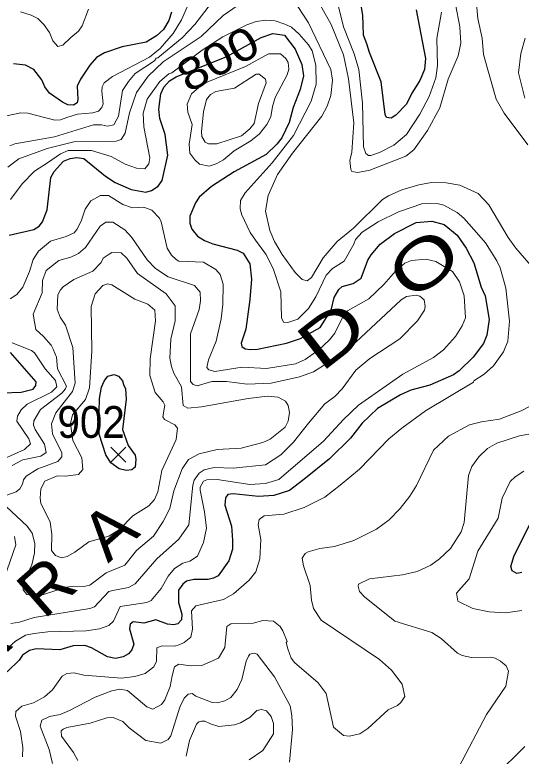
# Model space of a CAD drawing. Extents: x 294.2 to 320.3, y 7482.7 to 7510.7.
# Drawn here: x 307.293 to 308.568, y 7485.877 to 7487.743 of the extents above; entities that cross this region are included whole.
import ezdxf
from ezdxf.enums import TextEntityAlignment as Align

# ---------------------------------------------------------------- set-up
doc = ezdxf.new("R2010")
doc.units = 0
doc.header["$LTSCALE"] = 0.032
for name, color, linetype, lineweight in [('1', 7, 'Continuous', 25), ('2', 7, 'Continuous', 13), ('21', 7, 'Continuous', 25)]:
    doc.layers.add(name, color=color, linetype=linetype, lineweight=lineweight)
doc.layers.add('61', color=7, linetype='Continuous')

msp = doc.modelspace()

# ---------------------------------------------------------------- linework, layer by layer
at = {"layer": '1'}
for points in [[(308.1796, 7487.6694), (308.1712, 7487.6914), (308.1697, 7487.7183), (308.1691, 7487.7409), (308.1586, 7487.8093)], [(308.3036, 7487.7552), (308.3268, 7487.6325), (308.324, 7487.605), (308.3123, 7487.5776), (308.2922, 7487.5453), (308.2795, 7487.5179), (308.2523, 7487.4904)], [(307.6875, 7487.7491), (307.6808, 7487.7286), (307.6675, 7487.706), (307.6497, 7487.6899), (307.6236, 7487.6742), (307.5631, 7487.6624), (307.5193, 7487.6473), (307.4988, 7487.635), (307.4816, 7487.6162), (307.4589, 7487.5807), (307.4505, 7487.5629), (307.4522, 7487.5295), (307.45, 7487.5214), (307.4412, 7487.5155), (307.4267, 7487.5165), (307.4134, 7487.5225), (307.3806, 7487.5457), (307.3689, 7487.5618), (307.3612, 7487.579), (307.3412, 7487.6048), (307.3201, 7487.6156), (307.2895, 7487.6194)], [(307.2792, 7487.188), (307.3413, 7487.202), (307.3543, 7487.2111), (307.3632, 7487.2219), (307.3743, 7487.2515), (307.3842, 7487.3329), (307.3925, 7487.348), (307.416, 7487.3743), (307.4327, 7487.3813), (307.4493, 7487.384), (307.467, 7487.3808), (307.5211, 7487.3367), (307.546, 7487.3205), (307.586, 7487.3028), (307.6226, 7487.2964), (307.6376, 7487.3002), (307.6537, 7487.3115), (307.6643, 7487.3254), (307.6784, 7487.3895), (307.6718, 7487.4416), (307.6585, 7487.482), (307.6557, 7487.5056), (307.6606, 7487.5437), (307.6684, 7487.5604), (307.6822, 7487.5766), (307.6994, 7487.5868), (307.8267, 7487.6374), (307.9129, 7487.6858), (307.9427, 7487.696), (307.9716, 7487.6917), (307.9988, 7487.6562), (308.016, 7487.6175)], [(308.2523, 7487.4904), (308.2407, 7487.4824), (308.229, 7487.4845), (308.2251, 7487.492), (308.2157, 7487.5738), (308.1863, 7487.6479), (308.1796, 7487.6694)], [(308.016, 7487.6175), (308.0202, 7487.589), (308.0118, 7487.5551), (307.9938, 7487.5094), (307.9838, 7487.4713), (307.9649, 7487.4331), (307.9524, 7487.417)], [(307.9524, 7487.417), (307.9258, 7487.3912), (307.8451, 7487.3471), (307.7886, 7487.3104), (307.7575, 7487.2835), (307.7481, 7487.2696), (307.7334, 7487.2357), (307.7334, 7487.2185), (307.7389, 7487.2029), (307.7534, 7487.1857), (307.7703, 7487.1744), (307.7919, 7487.1663), (307.8532, 7487.1507), (307.8676, 7487.1432), (307.8849, 7487.1159), (307.8887, 7487.0776), (307.8845, 7487.0265), (307.8743, 7486.9517), (307.8632, 7486.9162), (307.8648, 7486.9076), (307.8731, 7486.9022), (307.8859, 7486.9001), (307.9037, 7486.9011), (307.9769, 7486.9162), (308.0127, 7486.928), (308.0615, 7486.9555), (308.0895, 7486.9996), (308.0973, 7487.0313), (308.1087, 7487.0512), (308.117, 7487.0587), (308.1447, 7487.0662), (308.1652, 7487.0797), (308.1819, 7487.1248), (308.1899, 7487.1388), (308.2127, 7487.1657), (308.2493, 7487.192), (308.3034, 7487.22), (308.3428, 7487.2232), (308.3736, 7487.2146), (308.4069, 7487.1877), (308.4296, 7487.1554), (308.4482, 7487.1183), (308.467, 7487.057), (308.4767, 7487.0355), (308.4872, 7486.9758), (308.4809, 7486.9365), (308.4726, 7486.9156), (308.4465, 7486.8806), (308.4118, 7486.8462), (308.3974, 7486.8365), (308.3381, 7486.8107), (308.2896, 7486.7978), (308.2641, 7486.7865), (308.2061, 7486.7515), (308.1672, 7486.7149), (308.1382, 7486.6773), (308.0856, 7486.6247), (308.0207, 7486.5729), (307.9846, 7486.5455), (307.945, 7486.5325), (307.9062, 7486.5304), (307.8426, 7486.5374), (307.8293, 7486.5352), (307.8232, 7486.5272), (307.8216, 7486.5089), (307.8388, 7486.4556), (307.8407, 7486.4207), (307.8407, 7486.3976), (307.8318, 7486.3685), (307.8049, 7486.3304), (307.7933, 7486.3245), (307.78, 7486.3212), (307.7434, 7486.3218), (307.7256, 7486.3173), (307.7162, 7486.3098), (307.7056, 7486.2947), (307.7051, 7486.2635), (307.714, 7486.2339), (307.7126, 7486.2199), (307.7037, 7486.2097), (307.6938, 7486.207), (307.6777, 7486.2086), (307.6483, 7486.2199), (307.6181, 7486.2118), (307.5914, 7486.2145), (307.5837, 7486.2092), (307.5815, 7486.1973), (307.5926, 7486.1586), (307.5876, 7486.1441), (307.5792, 7486.1339), (307.5656, 7486.1264), (307.5468, 7486.1226), (307.5268, 7486.1269), (307.4858, 7486.1495), (307.4694, 7486.1549)], [(307.2612, 7486.7911), (307.3089, 7486.7928), (307.3396, 7486.8008), (307.3463, 7486.8099), (307.3468, 7486.8191), (307.2822, 7486.8928)], [(308.5691, 7486.3388), (308.5569, 7486.3366), (308.5447, 7486.3436), (308.5414, 7486.3538), (308.5502, 7486.3819), (308.5924, 7486.4652)], [(307.4694, 7486.1549), (307.44, 7486.1543), (307.4068, 7486.1447), (307.3472, 7486.1469), (307.3305, 7486.1425), (307.3128, 7486.1307), (307.3045, 7486.1183)], [(307.3045, 7486.1183), (307.2751, 7486.0898), (307.2346, 7486.0704), (307.2205, 7486.0591), (307.2083, 7486.0397), (307.2022, 7486.0209), (307.2044, 7485.9994), (307.2324, 7485.9623), (307.2557, 7485.9215), (307.2578, 7485.8806), (307.2428, 7485.8499)]]:
    msp.add_lwpolyline(points, dxfattribs=at)
msp.add_lwpolyline([(307.5671, 7486.8119), (307.5716, 7486.8017), (307.5732, 7486.7753), (307.5641, 7486.699), (307.5786, 7486.6587), (307.5963, 7486.6345), (307.598, 7486.6237), (307.5958, 7486.6044), (307.5874, 7486.5974), (307.5736, 7486.5957), (307.5559, 7486.6), (307.5352, 7486.6147), (307.5219, 7486.6352), (307.5055, 7486.6874), (307.5044, 7486.7095), (307.5066, 7486.7773), (307.5117, 7486.8054), (307.5179, 7486.8205), (307.5274, 7486.8328), (307.5435, 7486.8371), (307.554, 7486.8328), (307.5645, 7486.8215)], close=True, dxfattribs=at)
at = {"layer": '2'}
for points in [[(307.769, 7487.8589), (307.7128, 7487.7299), (307.6917, 7487.6955), (307.6587, 7487.6577), (307.6325, 7487.6362), (307.5388, 7487.5878), (307.5185, 7487.5717), (307.5131, 7487.5617), (307.512, 7487.5509), (307.5154, 7487.5186), (307.5123, 7487.5094), (307.5035, 7487.5002), (307.4893, 7487.496), (307.4512, 7487.4929), (307.4239, 7487.4845), (307.4078, 7487.478), (307.3936, 7487.4772), (307.3261, 7487.4952), (307.308, 7487.496), (307.2722, 7487.4885)], [(308.3672, 7487.7491), (308.3557, 7487.6827), (308.357, 7487.615), (308.3531, 7487.5844), (308.3359, 7487.5371), (308.313, 7487.493), (308.2791, 7487.4418), (308.2475, 7487.4147), (308.2113, 7487.3958), (308.1897, 7487.3883), (308.1833, 7487.3883), (308.1769, 7487.3934), (308.1705, 7487.4107), (308.168, 7487.5205), (308.159, 7487.6048), (308.1475, 7487.6444), (308.1207, 7487.7121), (308.0901, 7487.8346)], [(307.2805, 7487.4126), (307.2933, 7487.4177), (307.3929, 7487.4356), (307.4912, 7487.4662), (307.5117, 7487.4662), (307.5263, 7487.4624), (307.5423, 7487.4656), (307.5538, 7487.4873), (307.5645, 7487.5523), (307.5795, 7487.5749), (307.5962, 7487.5953), (307.6444, 7487.6271), (307.6489, 7487.6335), (307.6534, 7487.6341), (307.7147, 7487.6846), (307.7466, 7487.7184), (307.8194, 7487.8142)], [(308.4502, 7487.8283), (308.4585, 7487.7338), (308.4693, 7487.684), (308.4726, 7487.643), (308.5051, 7487.5307), (308.5249, 7487.495), (308.5843, 7487.4158)], [(308.039, 7487.8091), (308.0895, 7487.7184)], [(307.2754, 7487.359), (307.3035, 7487.38), (307.375, 7487.4062), (307.4421, 7487.4234), (307.548, 7487.4247), (307.5608, 7487.4285), (307.571, 7487.4452), (307.5819, 7487.4962), (307.5997, 7487.5473), (307.6285, 7487.5882), (307.6663, 7487.6245), (307.7626, 7487.6884), (307.8175, 7487.7414), (307.8551, 7487.7669)], [(307.3074, 7487.7503), (307.3342, 7487.7421), (307.3508, 7487.7331), (307.3661, 7487.7184), (307.3808, 7487.698), (307.389, 7487.6769), (307.4012, 7487.6629), (307.414, 7487.6661), (307.4344, 7487.6859), (307.4536, 7487.7012), (307.4625, 7487.7146), (307.4784, 7487.7567)], [(308.0057, 7487.764), (308.032, 7487.7222), (308.0888, 7487.6048), (308.0926, 7487.578), (308.0888, 7487.5396), (308.0793, 7487.5128), (308.0658, 7487.4873), (307.9924, 7487.3947), (307.9541, 7487.3405), (307.9311, 7487.2881), (307.9241, 7487.2485), (307.935, 7487.2), (307.9465, 7487.1719), (307.9662, 7487.1393), (307.9988, 7487.094), (308.0161, 7487.0761)], [(308.1386, 7487.3532), (308.1418, 7487.3487), (308.1565, 7487.3462), (308.1872, 7487.3513), (308.2778, 7487.3871), (308.2976, 7487.403), (308.3321, 7487.4515), (308.3627, 7487.509), (308.3838, 7487.5805), (308.4093, 7487.6393), (308.4157, 7487.6712), (308.4132, 7487.7121), (308.4023, 7487.7695)], [(307.9727, 7487.7196), (307.9484, 7487.728), (307.9254, 7487.7293), (307.9011, 7487.7261), (307.8769, 7487.7178), (307.8169, 7487.6871), (307.7645, 7487.6539), (307.688, 7487.5963), (307.6808, 7487.5939), (307.6585, 7487.5747), (307.6266, 7487.5307), (307.6163, 7487.495), (307.6176, 7487.4605), (307.6329, 7487.3826), (307.6304, 7487.3679), (307.6202, 7487.3551), (307.5991, 7487.3564), (307.571, 7487.3672), (307.5359, 7487.3858), (307.4861, 7487.4011), (307.4272, 7487.4015), (307.4078, 7487.3929), (307.3756, 7487.3698), (307.3425, 7487.3494), (307.3118, 7487.3174), (307.2824, 7487.2779)], [(307.3878, 7486.0437), (307.4127, 7486.0782), (307.4242, 7486.0852), (307.4427, 7486.0864), (307.467, 7486.0807), (307.5615, 7486.0731), (307.5953, 7486.0769), (307.6215, 7486.0852), (307.6432, 7486.1012), (307.6495, 7486.1159), (307.6508, 7486.1495), (307.6642, 7486.1543), (307.6947, 7486.1538), (307.7069, 7486.157), (307.7198, 7486.1631), (307.7364, 7486.1765), (307.7402, 7486.1963), (307.7383, 7486.2429), (307.7492, 7486.255), (307.8186, 7486.2712), (307.8437, 7486.285), (307.8832, 7486.3195), (307.8998, 7486.3406), (307.91, 7486.3738), (307.9126, 7486.4217), (307.9056, 7486.4594), (307.9082, 7486.4721), (307.9209, 7486.4817), (307.9701, 7486.4861), (308.0212, 7486.5027), (308.0735, 7486.5283), (308.1125, 7486.5589), (308.161, 7486.5992), (308.235, 7486.6758), (308.267, 7486.7026), (308.327, 7486.746), (308.4476, 7486.8182), (308.4483, 7486.8214), (308.4745, 7486.8386), (308.4981, 7486.859), (308.523, 7486.8948), (308.5345, 7486.9216), (308.5383, 7486.9714), (308.5288, 7487.0544), (308.5147, 7487.1055), (308.5064, 7487.1234), (308.4777, 7487.1687), (308.4611, 7487.1885), (308.4234, 7487.2313), (308.4068, 7487.2453), (308.373, 7487.2638), (308.3596, 7487.267), (308.32, 7487.2676), (308.2587, 7487.2472), (308.2076, 7487.2217), (308.1673, 7487.1955), (308.1508, 7487.1776), (308.1469, 7487.1655), (308.122, 7487.1227), (308.0927, 7487.1042), (308.0767, 7487.087), (308.0505, 7487.0327), (308.0326, 7487.0033), (308.0052, 7486.9765), (307.9803, 7486.9682), (307.9694, 7486.9695), (307.9643, 7486.9804), (307.9624, 7487.0455), (307.9432, 7487.1042), (307.9248, 7487.14), (307.8986, 7487.1757), (307.8858, 7487.1949), (307.8641, 7487.2409), (307.8602, 7487.2549), (307.8615, 7487.2753), (307.873, 7487.2945), (307.9407, 7487.3698), (307.9943, 7487.4388), (308.039, 7487.5256), (308.0518, 7487.5678), (308.0505, 7487.6163), (308.0416, 7487.652), (308.0326, 7487.6674), (308.009, 7487.6942), (307.9893, 7487.7114), (307.9727, 7487.7196)], [(308.0895, 7487.7184), (308.1201, 7487.6418), (308.1329, 7487.5818), (308.1463, 7487.4707), (308.1412, 7487.3966), (308.1361, 7487.3762), (308.1386, 7487.3532)], [(308.5779, 7487.684), (308.5671, 7487.6456), (308.5613, 7487.5971), (308.5773, 7487.5326)], [(308.2191, 7487.2778), (308.2337, 7487.2875), (308.2676, 7487.3021), (308.3098, 7487.3149), (308.3417, 7487.3206), (308.3787, 7487.32), (308.4132, 7487.3136), (308.4592, 7487.2926), (308.486, 7487.2645), (308.5351, 7487.1821), (308.5543, 7487.1553), (308.6143, 7487.0857)], [(307.2818, 7487.0282), (307.2984, 7487.0391), (307.3131, 7487.0569), (307.3303, 7487.0966), (307.3392, 7487.1272), (307.3527, 7487.1476), (307.3827, 7487.1731), (307.4223, 7487.1846), (307.4427, 7487.1942), (307.4497, 7487.2025), (307.4605, 7487.223), (307.4702, 7487.2536), (307.4848, 7487.2741), (307.5091, 7487.2881), (307.5289, 7487.2881), (307.5653, 7487.2651), (307.5896, 7487.2568), (307.6177, 7487.2587), (307.638, 7487.2511), (307.6572, 7487.2306), (307.6617, 7487.2217), (307.677, 7487.1553), (307.6872, 7487.138), (307.6993, 7487.1266), (307.7064, 7487.1227), (307.7677, 7487.1202), (307.799, 7487.1016)], [(308.0161, 7487.0761), (308.0288, 7487.0735), (308.0403, 7487.0819), (308.0697, 7487.131), (308.1048, 7487.1719), (308.1456, 7487.2057), (308.2191, 7487.2778)], [(307.2862, 7486.6081), (307.3137, 7486.6228), (307.3584, 7486.6317), (307.3724, 7486.6407), (307.368, 7486.6624), (307.3443, 7486.6988), (307.3405, 7486.7096), (307.3412, 7486.7211), (307.3578, 7486.7492), (307.4114, 7486.79), (307.421, 7486.8009), (307.4229, 7486.808), (307.4005, 7486.8514), (307.398, 7486.8808), (307.3897, 7486.9012), (307.3846, 7486.9114), (307.3655, 7486.9331), (307.3463, 7486.951), (307.3392, 7486.9893), (307.3622, 7487.0429), (307.3629, 7487.0736), (307.3724, 7487.0991), (307.4037, 7487.1246), (307.4338, 7487.1329), (307.4535, 7487.1419), (307.4708, 7487.1572), (307.5078, 7487.2108), (307.5225, 7487.2204), (307.5398, 7487.2211), (307.5697, 7487.2019), (307.5876, 7487.1821), (307.626, 7487.1259), (307.647, 7487.1042), (307.679, 7487.0831), (307.7454, 7487.0614), (307.7594, 7487.0448), (307.7606, 7487.0225), (307.7575, 7487.0008), (307.7351, 7486.9395), (307.7358, 7486.8195), (307.742, 7486.8125), (307.7525, 7486.8092), (307.7894, 7486.8201), (307.8258, 7486.8201), (307.8782, 7486.813), (307.9382, 7486.8156), (308.0097, 7486.8316), (308.0454, 7486.8444), (308.1137, 7486.8878), (308.1514, 7486.9184), (308.2657, 7487.025), (308.2791, 7487.0339), (308.3034, 7487.0372), (308.3123, 7487.0346), (308.3238, 7487.0257), (308.3263, 7487.0084), (308.3244, 7486.9995)], [(307.2716, 7486.5053), (307.3239, 7486.4555), (307.3367, 7486.4377), (307.3437, 7486.4121), (307.3431, 7486.3879), (307.3361, 7486.3585), (307.3195, 7486.324), (307.315, 7486.3074), (307.3144, 7486.2953), (307.3233, 7486.2838), (307.3546, 7486.2805), (307.4236, 7486.3022), (307.4414, 7486.3048), (307.467, 7486.3035), (307.4823, 7486.3068), (307.5232, 7486.338), (307.5697, 7486.3572), (307.5991, 7486.3942), (307.6419, 7486.4306), (307.6668, 7486.467), (307.6834, 7486.5002), (307.6936, 7486.5449), (307.7141, 7486.5998), (307.7307, 7486.6234), (307.7568, 7486.6381), (307.8028, 7486.6483), (307.8628, 7486.6521), (307.9177, 7486.6662), (307.9356, 7486.6745), (307.9739, 7486.7051), (307.9815, 7486.7198), (307.9848, 7486.7416), (307.9815, 7486.7594), (307.9745, 7486.7703), (307.956, 7486.7805), (307.9292, 7486.7831), (307.8807, 7486.7773), (307.7632, 7486.7562), (307.7288, 7486.7524), (307.7172, 7486.7594), (307.7128, 7486.8066), (307.6936, 7486.8405), (307.6872, 7486.8578), (307.6834, 7486.8782), (307.686, 7486.9261), (307.6968, 7486.9727), (307.6969, 7487.01), (307.6741, 7487.0402), (307.6023, 7487.0914), (307.5755, 7487.1298), (307.5608, 7487.1438), (307.5378, 7487.1444), (307.5308, 7487.1406), (307.5155, 7487.1304), (307.5103, 7487.1195), (307.4893, 7487.0972), (307.4414, 7487.0768), (307.4146, 7487.0582), (307.4082, 7487.0506), (307.4012, 7487.0378), (307.3999, 7487.0021), (307.4076, 7486.9816), (307.4204, 7486.9612), (307.4395, 7486.905), (307.4452, 7486.8156), (307.4382, 7486.7945), (307.3967, 7486.7409), (307.3859, 7486.7135), (307.3884, 7486.6879), (307.4114, 7486.64), (307.4114, 7486.6298), (307.4018, 7486.6183), (307.3508, 7486.5998), (307.322, 7486.5816), (307.3148, 7486.5724), (307.3126, 7486.5611), (307.3059, 7486.5493), (307.2965, 7486.5423), (307.2729, 7486.5334)], [(307.7805, 7486.8744), (307.7766, 7486.8552), (307.7817, 7486.8488), (307.7964, 7486.845), (307.8654, 7486.8558), (307.9267, 7486.8526), (307.9995, 7486.8641), (308.0237, 7486.875), (308.0582, 7486.8993), (308.0856, 7486.9248), (308.0984, 7486.9414), (308.1207, 7486.9855), (308.1303, 7486.9976), (308.1846, 7487.0276), (308.2223, 7487.064), (308.251, 7487.0972), (308.2753, 7487.1176), (308.2919, 7487.1246), (308.3276, 7487.1278), (308.3532, 7487.1221), (308.3953, 7487.0965), (308.4126, 7487.0703), (308.424, 7487.0353), (308.4272, 7486.9797), (308.4189, 7486.9599), (308.4023, 7486.9331), (308.3723, 7486.8992), (308.3468, 7486.8801), (308.2702, 7486.8386), (308.1584, 7486.7601), (308.1207, 7486.7243), (308.0703, 7486.6694), (307.9574, 7486.5735), (307.9246, 7486.5627), (307.8847, 7486.5605), (307.8028, 7486.573), (307.7766, 7486.5724), (307.7677, 7486.5685), (307.76, 7486.5539), (307.76, 7486.5462), (307.7708, 7486.4913), (307.776, 7486.4504), (307.7683, 7486.4147), (307.753, 7486.3802), (307.7339, 7486.3674)], [(307.799, 7487.1016), (307.8098, 7487.0895), (307.8175, 7487.0646), (307.8168, 7487.0136), (307.813, 7486.9778), (307.8002, 7486.9216), (307.7805, 7486.8744)], [(308.3244, 7486.9995), (308.3072, 7486.9727), (308.2625, 7486.9273), (308.1872, 7486.8776), (308.1514, 7486.8482), (308.1169, 7486.8016), (308.0984, 7486.7824)], [(307.2652, 7486.6253), (307.3176, 7486.649), (307.3329, 7486.663), (307.3284, 7486.6758), (307.2984, 7486.7199), (307.3003, 7486.7326), (307.3093, 7486.7486), (307.3239, 7486.7626), (307.3859, 7486.7926), (307.3993, 7486.806), (307.3954, 7486.822), (307.3693, 7486.8514), (307.3431, 7486.8916), (307.3354, 7486.8974), (307.2869, 7486.9171)], [(308.6111, 7486.769), (308.5677, 7486.746), (308.5128, 7486.7249), (308.4681, 7486.7185), (308.4375, 7486.7103), (308.3845, 7486.6822), (308.3468, 7486.647), (308.304, 7486.5577), (308.2874, 7486.5309), (308.2631, 7486.5002), (308.2357, 7486.4715), (308.2038, 7486.4478), (308.1463, 7486.4197), (308.0978, 7486.4044), (308.0608, 7486.3993), (308.0314, 7486.391), (308.0243, 7486.3872), (308.0167, 7486.3751), (308.0199, 7486.3559), (308.0365, 7486.3061), (308.0397, 7486.2691), (308.0454, 7486.2487), (308.0639, 7486.2192), (308.2114, 7486.1203), (308.2414, 7486.0935), (308.2683, 7486.0577), (308.2746, 7486.0271), (308.265, 7486.0117), (308.2567, 7486.0041), (308.2331, 7485.9932), (308.1814, 7485.946), (308.1616, 7485.9326), (308.1348, 7485.9268), (308.1208, 7485.9288), (308.0952, 7485.9498), (308.0767, 7486.0341), (308.0569, 7486.0609), (307.9969, 7486.1126), (307.9892, 7486.1235), (307.9803, 7486.1465), (307.9764, 7486.1631), (307.9784, 7486.1657), (307.9675, 7486.1925), (307.9611, 7486.2027), (307.9439, 7486.2161), (307.9171, 7486.2186), (307.8935, 7486.2116), (307.8373, 7486.2097), (307.827, 7486.2033), (307.8219, 7486.1503), (307.806, 7486.1235), (307.7639, 7486.105), (307.7351, 7486.1037), (307.7058, 7486.1082), (307.6955, 7486.1018), (307.6891, 7486.0788), (307.684, 7486.052), (307.6706, 7486.0188), (307.6623, 7486.0066), (307.6406, 7485.9952), (307.6253, 7486.0009), (307.5768, 7486.0418), (307.5576, 7486.0456), (307.5372, 7486.0412), (307.4957, 7486.0252), (307.4312, 7485.9913), (307.407, 7485.9817), (307.3801, 7485.9766), (307.3609, 7485.9671), (307.3571, 7485.9524), (307.3795, 7485.8937), (307.3878, 7485.8579)], [(308.0984, 7486.7824), (308.0735, 7486.7632), (308.0326, 7486.7147)], [(308.0326, 7486.7147), (307.995, 7486.6668), (307.9624, 7486.6349), (307.9241, 7486.61), (307.8424, 7486.6017), (307.7947, 7486.6033), (307.7696, 7486.5972), (307.7568, 7486.5889), (307.7447, 7486.5711), (307.7415, 7486.559), (307.7313, 7486.4593), (307.7064, 7486.4229), (307.6508, 7486.3732), (307.5965, 7486.3106), (307.5793, 7486.3016), (307.5398, 7486.294), (307.5295, 7486.2908), (307.4938, 7486.2524), (307.4823, 7486.2486), (307.3418, 7486.2256), (307.3048, 7486.2141), (307.2831, 7486.211)], [(308.6482, 7486.6981), (308.5639, 7486.6828), (308.5064, 7486.6643), (308.4834, 7486.6509), (308.4611, 7486.6305), (308.4438, 7486.6062), (308.4355, 7486.5832), (308.424, 7486.4645), (308.4164, 7486.4415), (308.3896, 7486.3993), (308.3621, 7486.3732), (308.3404, 7486.3578), (308.3059, 7486.3418), (308.2689, 7486.3329), (308.1859, 7486.3233), (308.1584, 7486.31), (308.1572, 7486.3048), (308.161, 7486.2908), (308.1731, 7486.278), (308.2497, 7486.2161), (308.343, 7486.188), (308.366, 7486.1727), (308.4074, 7486.1362), (308.4196, 7486.1299), (308.4426, 7486.1248), (308.4911, 7486.126), (308.5026, 7486.1235), (308.516, 7486.1158), (308.53, 7486.1037), (308.5357, 7486.0903), (308.5288, 7486.0533), (308.4802, 7485.9818), (308.4106, 7485.849)], [(308.569, 7486.2435), (308.5281, 7486.2371), (308.4873, 7486.2397), (308.4464, 7486.248), (308.408, 7486.2671), (308.4049, 7486.287), (308.4368, 7486.3234), (308.4585, 7486.393), (308.5096, 7486.476), (308.5198, 7486.5258), (308.5402, 7486.5679), (308.5524, 7486.58), (308.5741, 7486.5941)], [(307.2664, 7486.324), (307.2958, 7486.4083), (307.2927, 7486.43)], [(307.7339, 7486.3674), (307.716, 7486.3623), (307.6949, 7486.3489), (307.6789, 7486.3297), (307.6617, 7486.2985), (307.6362, 7486.2684), (307.6253, 7486.2633), (307.5583, 7486.2531), (307.5417, 7486.2167), (307.5301, 7486.2052), (307.5066, 7486.1969), (307.4727, 7486.1918), (307.3763, 7486.1899), (307.3416, 7486.1855), (307.32, 7486.1812), (307.2945, 7486.1661), (307.2524, 7486.1286)], [(307.9848, 7485.8617), (307.9918, 7485.9435), (307.9905, 7485.9792), (307.9861, 7486.0035), (307.9471, 7486.0763), (307.903, 7486.1331), (307.896, 7486.1356), (307.8845, 7486.1331), (307.8813, 7486.1286), (307.8756, 7486.1159), (307.8647, 7486.0699), (307.8532, 7486.0444), (307.8366, 7486.0245), (307.822, 7486.0162), (307.8028, 7486.0111), (307.79, 7486.0118), (307.7492, 7486.0277), (307.7396, 7486.0348), (307.7294, 7486.0328), (307.7192, 7486.0226), (307.7083, 7485.9997), (307.686, 7485.9281), (307.679, 7485.9186), (307.6604, 7485.9096), (307.6227, 7485.916), (307.5813, 7485.9479), (307.5653, 7485.9639), (307.541, 7485.9741), (307.5244, 7485.9735), (307.4829, 7485.9594), (307.4242, 7485.9492), (307.4146, 7485.9447), (307.4101, 7485.9403), (307.4107, 7485.9269), (307.4408, 7485.886), (307.4516, 7485.8656)], [(307.3073, 7485.9384), (307.2945, 7485.9773), (307.2958, 7485.9894), (307.3112, 7486.0028), (307.3406, 7486.0111), (307.368, 7486.0264), (307.3878, 7486.0437)], [(307.7249, 7485.8764), (307.7332, 7485.916), (307.7504, 7485.9575), (307.7562, 7485.9633), (307.7632, 7485.9645), (307.7715, 7485.9645), (307.7855, 7485.9581), (307.8066, 7485.9518), (307.8462, 7485.9556), (307.8616, 7485.9607), (307.8852, 7485.9747), (307.9024, 7485.9913), (307.9139, 7485.9945), (307.9266, 7485.9907), (307.9381, 7485.9767), (307.9439, 7485.9588), (307.9439, 7485.9333), (307.9171, 7485.8911), (307.8833, 7485.8675)], [(307.3124, 7485.8751), (307.3137, 7485.8988), (307.3073, 7485.9384)], [(308.5025, 7485.8273), (308.5766, 7485.9007)]]:
    msp.add_lwpolyline(points, dxfattribs=at)
for points in [[(307.9094, 7487.4432), (307.8871, 7487.4253), (307.8456, 7487.4004), (307.8188, 7487.3781), (307.8003, 7487.3679), (307.7824, 7487.3615), (307.7581, 7487.3672), (307.746, 7487.3775), (307.7338, 7487.3947), (307.7319, 7487.4171), (307.7396, 7487.4669), (307.7287, 7487.4975), (307.7274, 7487.518), (307.7383, 7487.5441), (307.7621, 7487.5645), (307.7788, 7487.5742), (307.8736, 7487.6129), (307.9318, 7487.6446), (307.9618, 7487.6443), (307.9752, 7487.6329), (307.9815, 7487.6227), (307.9828, 7487.6061), (307.979, 7487.592), (307.9483, 7487.5346), (307.942, 7487.5116), (307.9375, 7487.486), (307.9279, 7487.4669)], [(307.9062, 7487.5192), (307.8954, 7487.4694), (307.8845, 7487.4554), (307.8641, 7487.4381), (307.8015, 7487.4177), (307.7811, 7487.4177), (307.7721, 7487.4221), (307.7639, 7487.4362), (307.7632, 7487.449), (307.7683, 7487.4988), (307.776, 7487.5294), (307.7855, 7487.5422), (307.799, 7487.5498), (307.8462, 7487.5581), (307.9005, 7487.5932), (307.9081, 7487.5932), (307.9241, 7487.5811), (307.926, 7487.5716)], [(307.3687, 7486.5685), (307.3584, 7486.5496), (307.3567, 7486.5259), (307.3589, 7486.5135), (307.3821, 7486.4657), (307.3865, 7486.4351), (307.3859, 7486.3942), (307.3955, 7486.3814), (307.4108, 7486.3757), (307.4248, 7486.3795), (307.4446, 7486.3904), (307.4797, 7486.4166), (307.5295, 7486.4306), (307.5564, 7486.4472), (307.5902, 7486.4817), (307.6304, 7486.5072), (307.6445, 7486.5225), (307.6534, 7486.5424), (307.6636, 7486.596), (307.6993, 7486.6739), (307.7026, 7486.702), (307.6962, 7486.7109), (307.6701, 7486.7243), (307.6657, 7486.7307), (307.6706, 7486.7598), (307.6668, 7486.7684), (307.6464, 7486.792), (307.6329, 7486.8348), (307.6342, 7486.8769), (307.6477, 7486.9727), (307.6457, 7486.9995), (307.6281, 7487.0148), (307.5954, 7487.0272), (307.5371, 7487.0633), (307.5266, 7487.066), (307.5144, 7487.0617), (307.4955, 7487.0407), (307.4855, 7487.0084), (307.4874, 7486.8961), (307.481, 7486.8041), (307.4714, 7486.7747), (307.4381, 7486.736), (307.4331, 7486.7144), (307.4392, 7486.6709), (307.4618, 7486.6279), (307.4644, 7486.5979), (307.4535, 7486.5857), (307.421, 7486.5819), (307.3999, 7486.5826)]]:
    msp.add_lwpolyline(points, close=True, dxfattribs=at)
at = {"layer": '21'}
for p, q in [((307.5348, 7486.6543), (307.5723, 7486.6168)), ((307.5723, 7486.6543), (307.5348, 7486.6168))]:
    msp.add_line(p, q, dxfattribs=at)

# ---------------------------------------------------------------- texts
at = {"layer": '61'}
for s, height, rotation, width, p in [('800', 0.08, 28.953, 1.2, (307.8238, 7487.5968)), ('D  O', 0.12, 37.871, 1.4, (308.2465, 7486.9823)), ('S  E  R  R  A', 0.12, 41.302, 1.05, (307.2536, 7486.1201))]:
    msp.add_text(s, height=height, rotation=rotation, dxfattribs=dict(at, width=width)).set_placement(p, align=Align.CENTER)
at = {"layer": '61', "width": 0.95}
msp.add_text('902', height=0.08, dxfattribs=at).set_placement((307.4853, 7486.6779), align=Align.CENTER)

doc.saveas('drawing.dxf')
